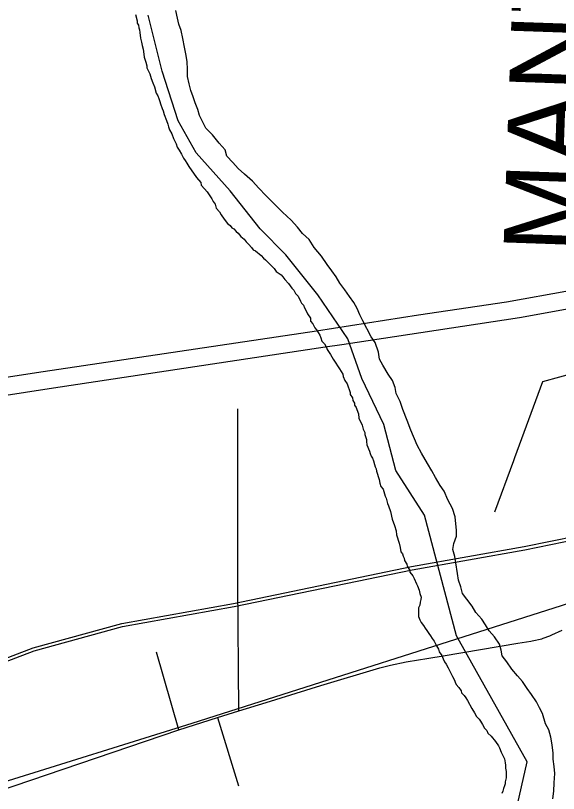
# Model space of a CAD drawing. Extents: x -59 to 82, y -3 to 49.
# Drawn here: x -52.915 to -52.531, y 46.954 to 47.505 of the extents above; entities that cross this region are included whole.
import ezdxf

# ---------------------------------------------------------------- set-up
doc = ezdxf.new("R2010")
doc.units = 0
for name, color, linetype in [('GM_X_City_Street', 7, 'Continuous'), ('GM_X_Corporation', 7, 'Continuous'), ('GM_X_County_Road_Text', 7, 'Continuous'), ('GM_X_Major_River', 7, 'Continuous'), ('GM_X_Rail_Line', 7, 'Continuous'), ('GM_X_State_Route', 7, 'Continuous'), ('GM_X_Township_Road', 7, 'Continuous'), ('GM_X_US_Route', 7, 'Continuous')]:
    doc.layers.add(name, color=color, linetype=linetype)

msp = doc.modelspace()

# ---------------------------------------------------------------- linework, layer by layer
at = {"layer": 'GM_X_City_Street'}
for p, q in [((-52.75779, 47.1026), (-52.75782, 47.2263)), ((-52.75712, 47.01254), (-52.75779, 47.1026)), ((-52.79954, 46.9991), (-52.81534, 47.05395)), ((-52.77205, 47.00773), (-52.75724, 46.95931))]:
    msp.add_line(p, q, dxfattribs=at)
at = {"layer": 'GM_X_Corporation'}
for p, q in [((-52.8113, 47.46571), (-52.82119, 47.50532)), ((-52.79999, 47.43033), (-52.8113, 47.46571)), ((-52.78726, 47.40769), (-52.79999, 47.43033)), ((-52.76322, 47.3808), (-52.78726, 47.40769)), ((-52.742, 47.35392), (-52.76322, 47.3808)), ((-52.72361, 47.33552), (-52.742, 47.35392)), ((-52.70099, 47.30721), (-52.72361, 47.33552)), ((-52.67977, 47.27608), (-52.70099, 47.30721)), ((-52.66988, 47.24778), (-52.67977, 47.27608)), ((-52.65433, 47.21523), (-52.66988, 47.24778)), ((-52.64585, 47.18269), (-52.65433, 47.21523)), ((-52.62561, 47.15119), (-52.64585, 47.18269)), ((-52.60294, 47.06559), (-52.62561, 47.15119)), ((-52.55268, 46.97631), (-52.60294, 47.06559)), ((-52.56251, 46.93385), (-52.55268, 46.97631))]:
    msp.add_line(p, q, dxfattribs=at)
at = {"layer": 'GM_X_Major_River'}
for p, q in [((-52.80054, 47.50316), (-52.80169, 47.50847)), ((-52.83008, 47.50576), (-52.82893, 47.50122)), ((-52.82893, 47.50122), (-52.82893, 47.4997)), ((-52.7994, 47.499), (-52.80054, 47.50316)), ((-52.82893, 47.4997), (-52.82817, 47.49819)), ((-52.82817, 47.49819), (-52.82779, 47.49629)), ((-52.82779, 47.49629), (-52.8274, 47.49478)), ((-52.79788, 47.49445), (-52.7994, 47.499)), ((-52.8274, 47.49478), (-52.82702, 47.49288)), ((-52.82702, 47.49288), (-52.82664, 47.48909)), ((-52.79673, 47.48876), (-52.79788, 47.49445)), ((-52.82664, 47.48909), (-52.82587, 47.48606)), ((-52.82587, 47.48606), (-52.82549, 47.48379)), ((-52.79558, 47.4827), (-52.79673, 47.48876)), ((-52.82549, 47.48379), (-52.82473, 47.48113)), ((-52.82473, 47.48113), (-52.82434, 47.47772)), ((-52.79443, 47.47777), (-52.79558, 47.4827)), ((-52.82434, 47.47772), (-52.82396, 47.47545)), ((-52.82396, 47.47545), (-52.82281, 47.47204)), ((-52.79366, 47.47247), (-52.79443, 47.47777)), ((-52.82281, 47.47204), (-52.82205, 47.46939)), ((-52.82205, 47.46939), (-52.82205, 47.46787)), ((-52.82205, 47.46787), (-52.82015, 47.46371)), ((-52.79327, 47.46678), (-52.79366, 47.47247)), ((-52.82015, 47.46371), (-52.819, 47.4603)), ((-52.79326, 47.46186), (-52.79327, 47.46678)), ((-52.819, 47.4603), (-52.81786, 47.45727)), ((-52.81786, 47.45727), (-52.81672, 47.45462)), ((-52.79211, 47.45655), (-52.79326, 47.46186)), ((-52.81672, 47.45462), (-52.81557, 47.45007)), ((-52.79097, 47.45201), (-52.79211, 47.45655)), ((-52.78945, 47.44746), (-52.79097, 47.45201)), ((-52.81557, 47.45007), (-52.81443, 47.44818)), ((-52.81443, 47.44818), (-52.81367, 47.44628)), ((-52.81367, 47.44628), (-52.81291, 47.44401)), ((-52.78792, 47.44329), (-52.78945, 47.44746)), ((-52.81291, 47.44401), (-52.81253, 47.44249)), ((-52.81253, 47.44249), (-52.81138, 47.43908)), ((-52.78602, 47.43837), (-52.78792, 47.44329)), ((-52.81138, 47.43908), (-52.81062, 47.43757)), ((-52.81062, 47.43757), (-52.80986, 47.43492)), ((-52.80986, 47.43492), (-52.80834, 47.43075)), ((-52.78487, 47.4342), (-52.78602, 47.43837)), ((-52.80834, 47.43075), (-52.8072, 47.4281)), ((-52.78031, 47.42511), (-52.78487, 47.4342)), ((-52.8072, 47.4281), (-52.80682, 47.4262)), ((-52.80682, 47.4262), (-52.80605, 47.42393)), ((-52.80605, 47.42393), (-52.80453, 47.42128)), ((-52.77576, 47.42057), (-52.78031, 47.42511)), ((-52.80453, 47.42128), (-52.80339, 47.41787)), ((-52.77083, 47.41452), (-52.77576, 47.42057)), ((-52.80339, 47.41787), (-52.80149, 47.41408)), ((-52.80149, 47.41408), (-52.80073, 47.41181)), ((-52.76665, 47.40997), (-52.77083, 47.41452)), ((-52.80073, 47.41181), (-52.79921, 47.40954)), ((-52.79921, 47.40954), (-52.79769, 47.40689)), ((-52.76551, 47.40543), (-52.76665, 47.40997)), ((-52.79769, 47.40689), (-52.79617, 47.40386)), ((-52.79617, 47.40386), (-52.79503, 47.40234)), ((-52.79503, 47.40234), (-52.79389, 47.40045)), ((-52.76133, 47.40089), (-52.76551, 47.40543)), ((-52.79389, 47.40045), (-52.79237, 47.39818)), ((-52.79237, 47.39818), (-52.78705, 47.39023)), ((-52.75754, 47.39672), (-52.76133, 47.40089)), ((-52.75298, 47.39256), (-52.75754, 47.39672)), ((-52.74729, 47.38764), (-52.75298, 47.39256)), ((-52.78705, 47.39023), (-52.78401, 47.38682)), ((-52.78401, 47.38682), (-52.78363, 47.38493)), ((-52.74274, 47.38272), (-52.74729, 47.38764)), ((-52.78363, 47.38493), (-52.78136, 47.38228)), ((-52.78136, 47.38228), (-52.77946, 47.38001)), ((-52.77946, 47.38001), (-52.77756, 47.37736)), ((-52.73781, 47.37742), (-52.74274, 47.38272)), ((-52.77756, 47.37736), (-52.77604, 47.37509)), ((-52.77604, 47.37509), (-52.77528, 47.37319)), ((-52.72605, 47.3657), (-52.73781, 47.37742)), ((-52.77528, 47.37319), (-52.77376, 47.3713)), ((-52.77376, 47.3713), (-52.773, 47.36865)), ((-52.773, 47.36865), (-52.77072, 47.366)), ((-52.77072, 47.366), (-52.76958, 47.36372)), ((-52.76958, 47.36372), (-52.7673, 47.3607)), ((-52.71998, 47.36002), (-52.72605, 47.3657)), ((-52.7673, 47.3607), (-52.76502, 47.35767)), ((-52.76502, 47.35767), (-52.76313, 47.35616)), ((-52.71543, 47.3551), (-52.71998, 47.36002)), ((-52.76313, 47.35616), (-52.76199, 47.35464)), ((-52.76199, 47.35464), (-52.76047, 47.35388)), ((-52.76047, 47.35388), (-52.75895, 47.35199)), ((-52.75895, 47.35199), (-52.75744, 47.35086)), ((-52.71201, 47.35056), (-52.71543, 47.3551)), ((-52.75744, 47.35086), (-52.75554, 47.34859)), ((-52.75554, 47.34859), (-52.75326, 47.3467)), ((-52.75326, 47.3467), (-52.75175, 47.3448)), ((-52.70708, 47.3464), (-52.71201, 47.35056)), ((-52.75175, 47.3448), (-52.74985, 47.34291)), ((-52.74985, 47.34291), (-52.74795, 47.34064)), ((-52.70366, 47.34072), (-52.70708, 47.3464)), ((-52.74795, 47.34064), (-52.74681, 47.33913)), ((-52.74681, 47.33913), (-52.7453, 47.33837)), ((-52.7453, 47.33837), (-52.74112, 47.33497)), ((-52.69835, 47.33466), (-52.70366, 47.34072)), ((-52.74112, 47.33497), (-52.73961, 47.33307)), ((-52.73961, 47.33307), (-52.73809, 47.33194)), ((-52.73809, 47.33194), (-52.73202, 47.32588)), ((-52.69454, 47.3286), (-52.69835, 47.33466)), ((-52.73202, 47.32588), (-52.7305, 47.32361)), ((-52.69113, 47.32406), (-52.69454, 47.3286)), ((-52.7305, 47.32361), (-52.72709, 47.32134)), ((-52.72709, 47.32134), (-52.72595, 47.31983)), ((-52.72595, 47.31983), (-52.72443, 47.31794)), ((-52.68809, 47.3199), (-52.69113, 47.32406)), ((-52.68543, 47.31535), (-52.68809, 47.3199)), ((-52.72443, 47.31794), (-52.72178, 47.31529)), ((-52.72178, 47.31529), (-52.7195, 47.31188)), ((-52.68202, 47.31081), (-52.68543, 47.31535)), ((-52.7195, 47.31188), (-52.71798, 47.31037)), ((-52.71798, 47.31037), (-52.71684, 47.30809)), ((-52.71684, 47.30809), (-52.71494, 47.3062)), ((-52.6786, 47.30588), (-52.68202, 47.31081)), ((-52.71494, 47.3062), (-52.71342, 47.30279)), ((-52.71342, 47.30279), (-52.71266, 47.30128)), ((-52.67556, 47.30172), (-52.6786, 47.30588)), ((-52.71266, 47.30128), (-52.71114, 47.29977)), ((-52.71114, 47.29977), (-52.71038, 47.29787)), ((-52.71038, 47.29787), (-52.70962, 47.29636)), ((-52.67328, 47.29756), (-52.67556, 47.30172)), ((-52.67138, 47.29301), (-52.67328, 47.29756)), ((-52.70962, 47.29636), (-52.70848, 47.2937)), ((-52.70848, 47.2937), (-52.7062, 47.29068)), ((-52.6691, 47.28884), (-52.67138, 47.29301)), ((-52.7062, 47.29068), (-52.7062, 47.2884)), ((-52.7062, 47.2884), (-52.70468, 47.28651)), ((-52.70468, 47.28651), (-52.70316, 47.28386)), ((-52.66339, 47.27748), (-52.6691, 47.28884)), ((-52.70316, 47.28386), (-52.70202, 47.28234)), ((-52.70202, 47.28234), (-52.69974, 47.27856)), ((-52.69974, 47.27856), (-52.69898, 47.27666)), ((-52.69898, 47.27666), (-52.69822, 47.27439)), ((-52.66036, 47.27332), (-52.66339, 47.27748)), ((-52.69822, 47.27439), (-52.69632, 47.2725)), ((-52.69632, 47.2725), (-52.6948, 47.26985)), ((-52.6948, 47.26985), (-52.69442, 47.26833)), ((-52.65807, 47.2665), (-52.66036, 47.27332)), ((-52.69442, 47.26833), (-52.69214, 47.26492)), ((-52.69214, 47.26492), (-52.69024, 47.26152)), ((-52.6573, 47.26157), (-52.65807, 47.2665)), ((-52.69024, 47.26152), (-52.68834, 47.25887)), ((-52.68834, 47.25887), (-52.6872, 47.25697)), ((-52.65502, 47.25741), (-52.6573, 47.26157)), ((-52.6872, 47.25697), (-52.68568, 47.2547)), ((-52.68568, 47.2547), (-52.6834, 47.25092)), ((-52.65122, 47.25097), (-52.65502, 47.25741)), ((-52.6834, 47.25092), (-52.68302, 47.2494)), ((-52.68302, 47.2494), (-52.68188, 47.24637)), ((-52.64818, 47.24643), (-52.65122, 47.25097)), ((-52.68188, 47.24637), (-52.68036, 47.2441)), ((-52.68036, 47.2441), (-52.67807, 47.23804)), ((-52.64628, 47.2415), (-52.64818, 47.24643)), ((-52.67807, 47.23804), (-52.67807, 47.23652)), ((-52.67807, 47.23652), (-52.67655, 47.23425)), ((-52.64551, 47.23733), (-52.64628, 47.2415)), ((-52.64285, 47.23165), (-52.64551, 47.23733)), ((-52.67655, 47.23425), (-52.67617, 47.23235)), ((-52.67617, 47.23235), (-52.67503, 47.23046)), ((-52.64095, 47.22597), (-52.64285, 47.23165)), ((-52.67503, 47.23046), (-52.67503, 47.22894)), ((-52.67503, 47.22894), (-52.67389, 47.22743)), ((-52.67389, 47.22743), (-52.67351, 47.22591)), ((-52.67351, 47.22591), (-52.67236, 47.22288)), ((-52.6379, 47.21802), (-52.64095, 47.22597)), ((-52.67236, 47.22288), (-52.67197, 47.21985)), ((-52.67197, 47.21985), (-52.66969, 47.21493)), ((-52.66969, 47.21493), (-52.66893, 47.2119)), ((-52.63524, 47.2112), (-52.6379, 47.21802)), ((-52.66893, 47.2119), (-52.66779, 47.20963)), ((-52.66779, 47.20963), (-52.66779, 47.20811)), ((-52.63067, 47.20059), (-52.63524, 47.2112)), ((-52.66779, 47.20811), (-52.66664, 47.2047)), ((-52.66664, 47.2047), (-52.66664, 47.20318)), ((-52.66664, 47.20318), (-52.66626, 47.20091)), ((-52.66626, 47.20091), (-52.66435, 47.19636)), ((-52.62763, 47.19491), (-52.63067, 47.20059)), ((-52.66435, 47.19636), (-52.66397, 47.19485)), ((-52.66397, 47.19485), (-52.66321, 47.19295)), ((-52.66321, 47.19295), (-52.66245, 47.19144)), ((-52.62345, 47.18771), (-52.62763, 47.19491)), ((-52.66245, 47.19144), (-52.66169, 47.18955)), ((-52.66169, 47.18955), (-52.66093, 47.18689)), ((-52.66093, 47.18689), (-52.66054, 47.18538)), ((-52.62041, 47.18242), (-52.62345, 47.18771)), ((-52.66054, 47.18538), (-52.65978, 47.18386)), ((-52.65978, 47.18386), (-52.6594, 47.18235)), ((-52.6594, 47.18235), (-52.6575, 47.17629)), ((-52.61775, 47.17787), (-52.62041, 47.18242)), ((-52.6575, 47.17629), (-52.65711, 47.17363)), ((-52.61433, 47.17219), (-52.61775, 47.17787)), ((-52.65711, 47.17363), (-52.65635, 47.17136)), ((-52.65635, 47.17136), (-52.65483, 47.16947)), ((-52.61167, 47.16802), (-52.61433, 47.17219)), ((-52.65483, 47.16947), (-52.65331, 47.16454)), ((-52.60901, 47.16196), (-52.61167, 47.16802)), ((-52.65331, 47.16454), (-52.65255, 47.16303)), ((-52.65255, 47.16303), (-52.65178, 47.15924)), ((-52.65178, 47.15924), (-52.65102, 47.15772)), ((-52.60559, 47.15591), (-52.60901, 47.16196)), ((-52.65102, 47.15772), (-52.6495, 47.15356)), ((-52.6495, 47.15356), (-52.64835, 47.14825)), ((-52.60368, 47.14984), (-52.60559, 47.15591)), ((-52.64835, 47.14825), (-52.64683, 47.1437)), ((-52.60329, 47.14492), (-52.60368, 47.14984)), ((-52.64683, 47.1437), (-52.64568, 47.13992)), ((-52.60291, 47.14037), (-52.60329, 47.14492)), ((-52.64568, 47.13992), (-52.6453, 47.13726)), ((-52.6453, 47.13726), (-52.64339, 47.1312)), ((-52.6029, 47.1362), (-52.60291, 47.14037)), ((-52.60478, 47.13089), (-52.6029, 47.1362)), ((-52.64339, 47.1312), (-52.64263, 47.12817)), ((-52.64263, 47.12817), (-52.64224, 47.12514)), ((-52.60553, 47.12672), (-52.60478, 47.13089)), ((-52.604, 47.12179), (-52.60553, 47.12672)), ((-52.64224, 47.12514), (-52.64111, 47.12363)), ((-52.64111, 47.12363), (-52.64072, 47.12211)), ((-52.64072, 47.12211), (-52.63996, 47.12059)), ((-52.63996, 47.12059), (-52.63958, 47.11908)), ((-52.60323, 47.11725), (-52.604, 47.12179)), ((-52.63958, 47.11908), (-52.63806, 47.11643)), ((-52.63806, 47.11643), (-52.63768, 47.11491)), ((-52.60208, 47.10967), (-52.60323, 47.11725)), ((-52.63768, 47.11491), (-52.63616, 47.11226)), ((-52.63616, 47.11226), (-52.63578, 47.11075)), ((-52.63578, 47.11075), (-52.63388, 47.10809)), ((-52.60131, 47.10512), (-52.60208, 47.10967)), ((-52.63388, 47.10809), (-52.63274, 47.1062)), ((-52.63274, 47.1062), (-52.63122, 47.10242)), ((-52.59979, 47.1002), (-52.60131, 47.10512)), ((-52.63122, 47.10242), (-52.63046, 47.1009)), ((-52.63046, 47.1009), (-52.62932, 47.09787)), ((-52.59865, 47.09565), (-52.59979, 47.1002)), ((-52.62932, 47.09787), (-52.62893, 47.09559)), ((-52.62893, 47.09559), (-52.62779, 47.09294)), ((-52.62779, 47.09294), (-52.62816, 47.09143)), ((-52.59561, 47.09148), (-52.59865, 47.09565)), ((-52.62854, 47.08953), (-52.62891, 47.08726)), ((-52.62816, 47.09143), (-52.62854, 47.08953)), ((-52.59181, 47.08656), (-52.59561, 47.09148)), ((-52.62891, 47.08726), (-52.62967, 47.08536)), ((-52.62967, 47.08536), (-52.62966, 47.08384)), ((-52.62966, 47.08384), (-52.62965, 47.0793)), ((-52.58915, 47.08202), (-52.59181, 47.08656)), ((-52.58498, 47.07748), (-52.58915, 47.08202)), ((-52.62965, 47.0793), (-52.62889, 47.07702)), ((-52.62889, 47.07702), (-52.62775, 47.07513)), ((-52.58232, 47.07331), (-52.58498, 47.07748)), ((-52.62775, 47.07513), (-52.62623, 47.07286)), ((-52.62623, 47.07286), (-52.62509, 47.07096)), ((-52.62509, 47.07096), (-52.62395, 47.06945)), ((-52.57966, 47.06915), (-52.58232, 47.07331)), ((-52.62395, 47.06945), (-52.62243, 47.06718)), ((-52.62243, 47.06718), (-52.62129, 47.06566)), ((-52.62129, 47.06566), (-52.62015, 47.06377)), ((-52.57586, 47.06499), (-52.57966, 47.06915)), ((-52.62015, 47.06377), (-52.61864, 47.06188)), ((-52.61864, 47.06188), (-52.61788, 47.06036)), ((-52.61788, 47.06036), (-52.61711, 47.05847)), ((-52.57245, 47.05968), (-52.57586, 47.06499)), ((-52.61711, 47.05847), (-52.6156, 47.0562)), ((-52.6156, 47.0562), (-52.61521, 47.0543)), ((-52.5713, 47.05552), (-52.57245, 47.05968)), ((-52.57054, 47.05135), (-52.5713, 47.05552)), ((-52.61521, 47.0543), (-52.61331, 47.05165)), ((-52.61331, 47.05165), (-52.61217, 47.04938)), ((-52.61217, 47.04938), (-52.61141, 47.04711)), ((-52.56712, 47.04718), (-52.57054, 47.05135)), ((-52.61141, 47.04711), (-52.61027, 47.04559)), ((-52.61027, 47.04559), (-52.60875, 47.04294)), ((-52.5637, 47.04188), (-52.56712, 47.04718)), ((-52.60875, 47.04294), (-52.60571, 47.03688)), ((-52.55953, 47.03734), (-52.5637, 47.04188)), ((-52.60571, 47.03688), (-52.60419, 47.03423)), ((-52.60419, 47.03423), (-52.60381, 47.03272)), ((-52.60381, 47.03272), (-52.60305, 47.0312)), ((-52.55611, 47.03318), (-52.55953, 47.03734)), ((-52.55269, 47.02826), (-52.55611, 47.03318)), ((-52.60305, 47.0312), (-52.60115, 47.02893)), ((-52.60115, 47.02893), (-52.59963, 47.02666)), ((-52.54965, 47.02409), (-52.55269, 47.02826)), ((-52.59963, 47.02666), (-52.59925, 47.02514)), ((-52.59925, 47.02514), (-52.59735, 47.02325)), ((-52.59735, 47.02325), (-52.59621, 47.02174)), ((-52.59621, 47.02174), (-52.59507, 47.01984)), ((-52.54624, 47.01879), (-52.54965, 47.02409)), ((-52.59507, 47.01984), (-52.59204, 47.01416)), ((-52.54396, 47.01462), (-52.54624, 47.01879)), ((-52.59204, 47.01416), (-52.59014, 47.01113)), ((-52.59014, 47.01113), (-52.58861, 47.00848)), ((-52.54205, 47.01046), (-52.54396, 47.01462)), ((-52.53977, 47.00326), (-52.54205, 47.01046)), ((-52.58861, 47.00848), (-52.58672, 47.00659)), ((-52.58672, 47.00659), (-52.58596, 47.00507)), ((-52.58596, 47.00507), (-52.58444, 47.00281)), ((-52.58444, 47.00281), (-52.58292, 47.00015)), ((-52.58292, 47.00015), (-52.5814, 46.99864)), ((-52.53749, 46.99909), (-52.53977, 47.00326)), ((-52.5814, 46.99864), (-52.58064, 46.99674)), ((-52.58064, 46.99674), (-52.57836, 46.99447)), ((-52.57836, 46.99447), (-52.57533, 46.99069)), ((-52.53596, 46.99379), (-52.53749, 46.99909)), ((-52.53519, 46.98849), (-52.53596, 46.99379)), ((-52.57533, 46.99069), (-52.57305, 46.98766)), ((-52.53442, 46.98242), (-52.53519, 46.98849)), ((-52.57305, 46.98766), (-52.57229, 46.98615)), ((-52.57229, 46.98615), (-52.57115, 46.98312)), ((-52.57115, 46.98312), (-52.56886, 46.97857)), ((-52.56886, 46.97857), (-52.56848, 46.97554)), ((-52.53441, 46.97825), (-52.53442, 46.98242)), ((-52.53365, 46.97295), (-52.53441, 46.97825)), ((-52.56848, 46.97554), (-52.5681, 46.97402)), ((-52.5681, 46.97402), (-52.56809, 46.97175)), ((-52.56809, 46.97175), (-52.56771, 46.96948)), ((-52.53326, 46.96802), (-52.53365, 46.97295)), ((-52.56771, 46.96948), (-52.5677, 46.96493)), ((-52.53362, 46.96157), (-52.53326, 46.96802)), ((-52.56845, 46.96076), (-52.56882, 46.95924)), ((-52.5677, 46.96493), (-52.56845, 46.96227)), ((-52.56845, 46.96227), (-52.56845, 46.96076)), ((-52.53399, 46.95551), (-52.53362, 46.96157)), ((-52.56995, 46.95545), (-52.57071, 46.95393)), ((-52.56958, 46.95734), (-52.56995, 46.95545)), ((-52.56882, 46.95924), (-52.56958, 46.95734)), ((-52.53473, 46.9502), (-52.53399, 46.95551))]:
    msp.add_line(p, q, dxfattribs=at)
at = {"layer": 'GM_X_Rail_Line'}
for p, q in [((-52.3179, 47.15408), (-52.79021, 47.00356)), ((-52.55497, 47.12885), (-52.48121, 47.14376)), ((-52.55453, 47.12658), (-52.48072, 47.14149)), ((-52.63474, 47.11468), (-52.55497, 47.12885)), ((-52.6343, 47.11241), (-52.55453, 47.12658)), ((-52.76074, 47.08858), (-52.63474, 47.11468)), ((-52.76029, 47.08631), (-52.6343, 47.11241)), ((-52.83983, 47.0744), (-52.76074, 47.08858)), ((-52.83932, 47.07214), (-52.76029, 47.08631)), ((-52.90267, 47.05719), (-52.83983, 47.0744)), ((-52.90194, 47.05499), (-52.83932, 47.07214)), ((-52.94384, 47.04146), (-52.90267, 47.05719)), ((-52.94295, 47.03932), (-52.90194, 47.05499)), ((-52.79021, 47.00356), (-53.02702, 46.92963))]:
    msp.add_line(p, q, dxfattribs=at)
at = {"layer": 'GM_X_State_Route'}
for p, q in [((-52.56741, 47.3022), (-52.52289, 47.31018)), ((-52.62975, 47.29306), (-52.56741, 47.3022)), ((-52.55822, 47.291), (-52.51788, 47.29834)), ((-52.70198, 47.28175), (-52.62975, 47.29306)), ((-52.61713, 47.28206), (-52.55822, 47.291)), ((-52.8955, 47.25284), (-52.70198, 47.28175)), ((-52.68395, 47.27205), (-52.61713, 47.28206)), ((-52.88834, 47.24122), (-52.69591, 47.27026)), ((-52.69591, 47.27026), (-52.68395, 47.27205)), ((-53.10693, 47.22118), (-52.8955, 47.25284)), ((-53.10272, 47.20875), (-52.88834, 47.24122))]:
    msp.add_line(p, q, dxfattribs=at)
at = {"layer": 'GM_X_Township_Road'}
for p, q in [((-52.54163, 47.24572), (-52.48885, 47.26044)), ((-52.56152, 47.19183), (-52.54163, 47.24572)), ((-52.57574, 47.15332), (-52.56223, 47.18991)), ((-52.56223, 47.18991), (-52.56152, 47.19183))]:
    msp.add_line(p, q, dxfattribs=at)
at = {"layer": 'GM_X_US_Route'}
for p, q in [((-52.54135, 47.06389), (-52.53675, 47.06565)), ((-52.53675, 47.06565), (-52.53524, 47.06621)), ((-52.53524, 47.06621), (-52.52803, 47.06964)), ((-52.6124, 47.05143), (-52.5593, 47.06035)), ((-52.5593, 47.06035), (-52.55028, 47.06186)), ((-52.55028, 47.06186), (-52.54929, 47.06208)), ((-52.54929, 47.06208), (-52.5423, 47.06355)), ((-52.5423, 47.06355), (-52.54135, 47.06389)), ((-52.62967, 47.04859), (-52.62376, 47.04959)), ((-52.62376, 47.04959), (-52.62248, 47.0498)), ((-52.62248, 47.0498), (-52.6124, 47.05143)), ((-52.65726, 47.04303), (-52.64947, 47.04472)), ((-52.64947, 47.04472), (-52.63855, 47.0471)), ((-52.63855, 47.0471), (-52.62967, 47.04859)), ((-52.69895, 47.0303), (-52.65726, 47.04303)), ((-52.73773, 47.01846), (-52.69895, 47.0303)), ((-52.75712, 47.01254), (-52.73773, 47.01846)), ((-52.77205, 47.00773), (-52.75712, 47.01254)), ((-52.79954, 46.9991), (-52.77205, 47.00773)), ((-52.93226, 46.95396), (-52.79954, 46.9991))]:
    msp.add_line(p, q, dxfattribs=at)

# ---------------------------------------------------------------- texts
at = {"layer": 'GM_X_County_Road_Text'}
msp.add_text('MANTLE', height=0.056818, rotation=88.0248, dxfattribs=at).set_placement((-52.51281, 47.33612))

doc.saveas('drawing.dxf')
